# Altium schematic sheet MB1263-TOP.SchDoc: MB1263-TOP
size A3; CompanyName: STMicroelectronics; DocumentNumber: MB1263; Revision: C-04; SheetNumber: 2; SheetTotal: 11; Project: STM32MP157-EVAL
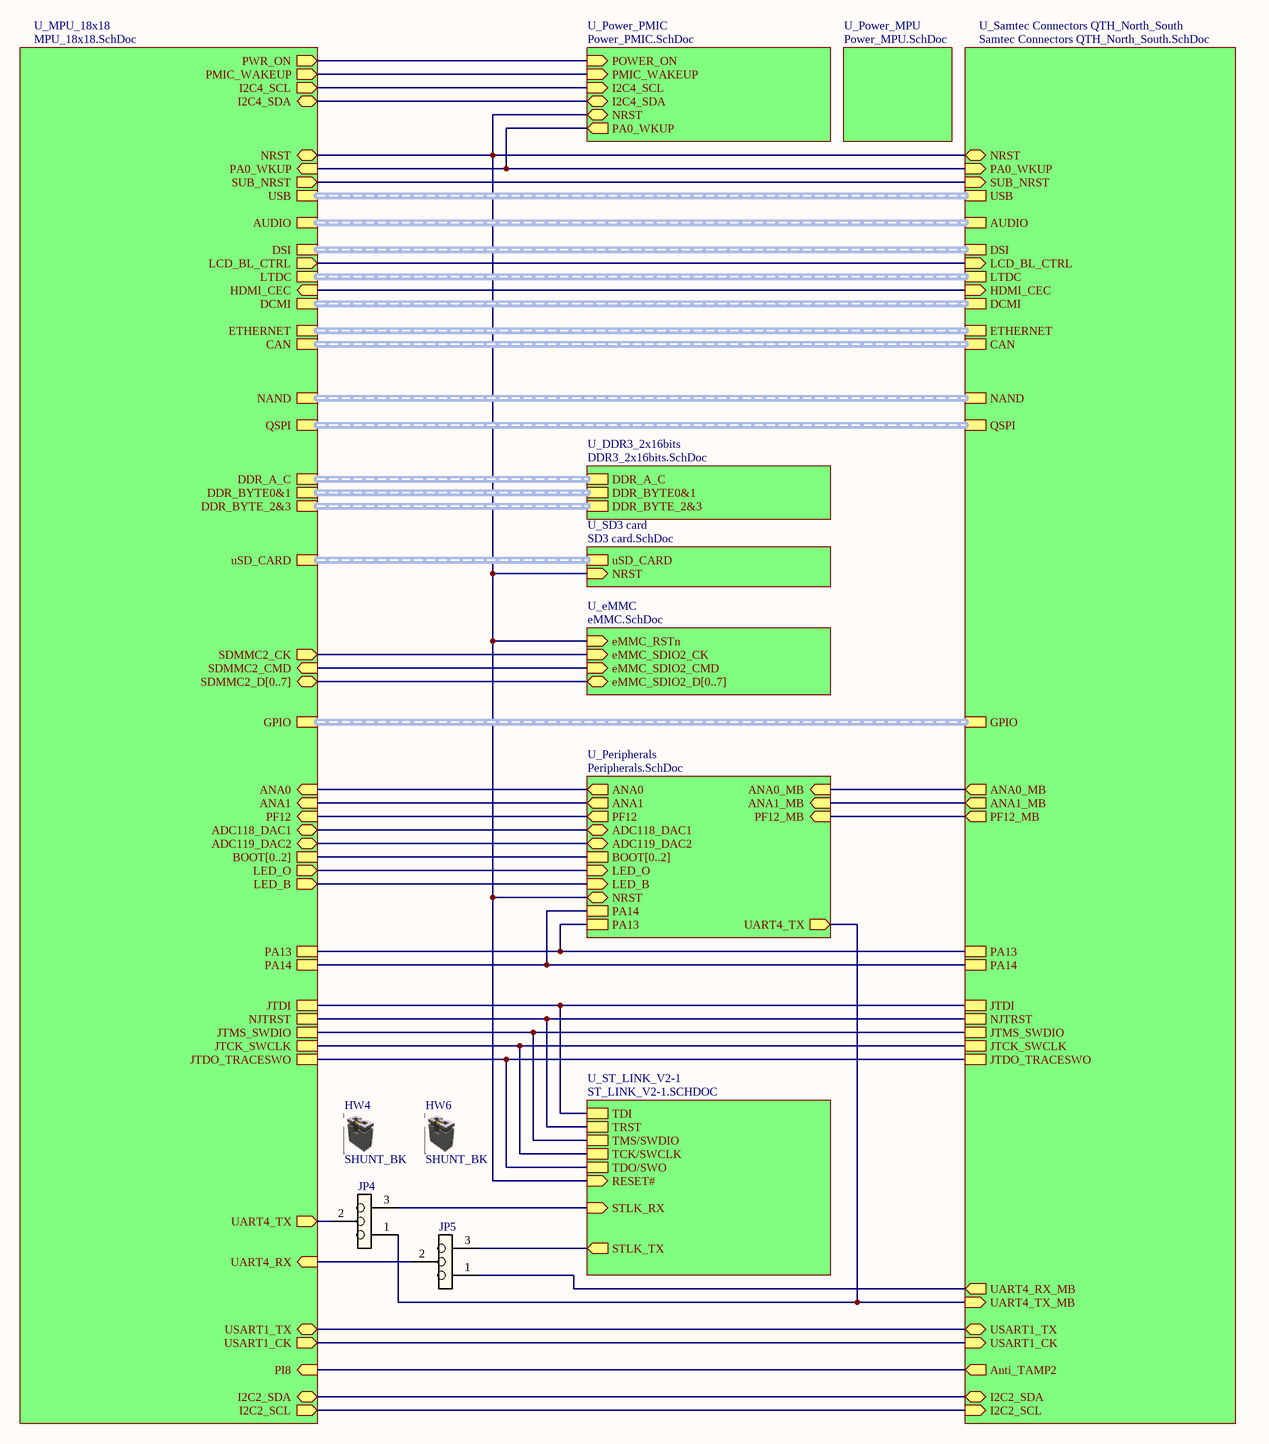
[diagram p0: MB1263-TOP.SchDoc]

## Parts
HW4  SHUNT_BK  (mechanical)
HW6  SHUNT_BK  (mechanical)
JP4  Header 3 pins  [CON_SAMTEC_TSW-103-07-F-S]  (value not drawn)
JP5  Header 3 pins  [CON_SAMTEC_TSW-103-07-F-S]  (value not drawn)

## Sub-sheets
U_DDR3_2x16bits = DDR3_2x16bits.SchDoc: DDR_A_C (harness DDR_A_C), DDR_BYTE0&1 (harness DDR_BYTE_0&1), DDR_BYTE_2&3 (harness DDR_BYTE_2&3)
U_eMMC = eMMC.SchDoc: eMMC_SDIO2_CK (in), eMMC_SDIO2_D[0..7] (bidir), eMMC_RSTn (in), eMMC_SDIO2_CMD (in)
U_MPU_18x18 = MPU_18x18.SchDoc: DDR_BYTE0&1 (harness DDR_BYTE_0&1), DDR_BYTE_2&3 (harness DDR_BYTE_2&3), DDR_A_C (harness DDR_A_C), ANA0 (in), ADC118_DAC1 (bidir), PWR_ON (out), SDMMC2_CK (out), SDMMC2_D[0..7] (bidir), SDMMC2_CMD (in), DSI (harness DSI), LCD_BL_CTRL (out), HDMI_CEC (in), USART1_TX (bidir), USART1_CK (out), CAN (harness CAN), JTMS_SWDIO, JTDI, JTDO_TRACESWO, NJTRST, JTCK_SWCLK, PA13, PA14, I2C4_SDA (bidir), I2C4_SCL (out), PA0_WKUP (in), PMIC_WAKEUP (out), NRST (bidir), UART4_TX (out), UART4_RX (in), ADC119_DAC2 (bidir), ANA1 (in), GPIO (harness GPIO), PI8 (in), USB (harness USB), NAND (harness NAND), LTDC (harness LTDC), DCMI (harness DCMI), ETHERNET (harness ETHERNET), QSPI (harness QSPI), AUDIO (harness AUDIO), uSD_CARD (harness uSD_CARD), PF12 (in), BOOT[0..2], I2C2_SDA (bidir), I2C2_SCL (out), LED_O (out), LED_B (out), SUB_NRST (out)
U_Peripherals = Peripherals.SchDoc: ADC118_DAC1 (bidir), ADC119_DAC2 (bidir), NRST (bidir), ANA0 (out), ANA1 (out), BOOT[0..2], PA13, PA14, UART4_TX (out), ANA0_MB (in), ANA1_MB (in), PF12 (out), PF12_MB (in), LED_O (in), LED_B (in)
U_Power_MPU = Power_MPU.SchDoc: no entries
U_Power_PMIC = Power_PMIC.SchDoc: I2C4_SDA (bidir), I2C4_SCL (in), PA0_WKUP (out), NRST (bidir), POWER_ON (in), PMIC_WAKEUP (in)
U_Samtec Connectors QTH_North_South = Samtec Connectors QTH_North_South.SchDoc: Anti_TAMP2 (out), USART1_TX (bidir), USART1_CK (in), GPIO (harness GPIO), LCD_BL_CTRL (in), DSI (harness DSI), JTMS_SWDIO, JTCK_SWCLK, JTDI, NJTRST, JTDO_TRACESWO, NRST (bidir), PA0_WKUP (in), CAN (harness CAN), UART4_TX_MB (in), UART4_RX_MB (out), PA13, PA14, HDMI_CEC (in), USB (harness USB), NAND (harness NAND), LTDC (harness LTDC), DCMI (harness DCMI), ETHERNET (harness ETHERNET), QSPI (harness QSPI), AUDIO (harness AUDIO), PF12_MB (out), ANA0_MB (out), ANA1_MB (out), I2C2_SCL (in), I2C2_SDA (bidir), SUB_NRST (in)
U_SD3 card = SD3 card.SchDoc: uSD_CARD (harness uSD_CARD), NRST (in)
U_ST_LINK_V2-1 = ST_LINK_V2-1.SCHDOC: STLK_RX (in), STLK_TX (out), TDI, TRST, TMS/SWDIO, TCK/SWCLK, TDO/SWO, RESET# (in)

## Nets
NetJP4_1: JP4.1 ; sheet U_Peripherals/UART4_TX, sheet U_Samtec Connectors QTH_North_South/UART4_TX_MB
NetJP4_2: JP4.2 ; sheet U_MPU_18x18/UART4_TX
NetJP4_3: JP4.3 ; sheet U_ST_LINK_V2-1/STLK_RX
NetJP5_1: JP5.1 ; sheet U_Samtec Connectors QTH_North_South/UART4_RX_MB
NetJP5_2: JP5.2 ; sheet U_MPU_18x18/UART4_RX
NetJP5_3: JP5.3 ; sheet U_ST_LINK_V2-1/STLK_TX
(unnamed): sheet U_eMMC/eMMC_SDIO2_CK, sheet U_MPU_18x18/SDMMC2_CK
(unnamed): sheet U_eMMC/eMMC_RSTn, sheet U_Power_PMIC/NRST, sheet U_MPU_18x18/NRST, sheet U_SD3 card/NRST, sheet U_Peripherals/NRST, sheet U_ST_LINK_V2-1/RESET#, sheet U_Samtec Connectors QTH_North_South/NRST  [a separate net that carries the same name]
(unnamed): sheet U_eMMC/eMMC_SDIO2_CMD, sheet U_MPU_18x18/SDMMC2_CMD  [a separate net that carries the same name]
(unnamed): sheet U_Power_PMIC/I2C4_SDA, sheet U_MPU_18x18/I2C4_SDA  [a separate net that carries the same name]
(unnamed): sheet U_Power_PMIC/I2C4_SCL, sheet U_MPU_18x18/I2C4_SCL  [a separate net that carries the same name]
(unnamed): sheet U_Power_PMIC/PA0_WKUP, sheet U_MPU_18x18/PA0_WKUP, sheet U_Samtec Connectors QTH_North_South/PA0_WKUP  [a separate net that carries the same name]
(unnamed): sheet U_Power_PMIC/POWER_ON, sheet U_MPU_18x18/PWR_ON  [a separate net that carries the same name]
(unnamed): sheet U_Power_PMIC/PMIC_WAKEUP, sheet U_MPU_18x18/PMIC_WAKEUP  [a separate net that carries the same name]
(unnamed): sheet U_MPU_18x18/ANA0, sheet U_Peripherals/ANA0  [a separate net that carries the same name]
(unnamed): sheet U_MPU_18x18/ADC118_DAC1, sheet U_Peripherals/ADC118_DAC1  [a separate net that carries the same name]
(unnamed): sheet U_MPU_18x18/LCD_BL_CTRL, sheet U_Samtec Connectors QTH_North_South/LCD_BL_CTRL  [a separate net that carries the same name]
(unnamed): sheet U_MPU_18x18/HDMI_CEC, sheet U_Samtec Connectors QTH_North_South/HDMI_CEC  [a separate net that carries the same name]
(unnamed): sheet U_MPU_18x18/USART1_TX, sheet U_Samtec Connectors QTH_North_South/USART1_TX  [a separate net that carries the same name]
(unnamed): sheet U_MPU_18x18/USART1_CK, sheet U_Samtec Connectors QTH_North_South/USART1_CK  [a separate net that carries the same name]
(unnamed): sheet U_MPU_18x18/JTMS_SWDIO, sheet U_ST_LINK_V2-1/TMS/SWDIO, sheet U_Samtec Connectors QTH_North_South/JTMS_SWDIO  [a separate net that carries the same name]
(unnamed): sheet U_MPU_18x18/JTDI, sheet U_ST_LINK_V2-1/TDI, sheet U_Samtec Connectors QTH_North_South/JTDI  [a separate net that carries the same name]
(unnamed): sheet U_MPU_18x18/JTDO_TRACESWO, sheet U_ST_LINK_V2-1/TDO/SWO, sheet U_Samtec Connectors QTH_North_South/JTDO_TRACESWO  [a separate net that carries the same name]
(unnamed): sheet U_MPU_18x18/NJTRST, sheet U_ST_LINK_V2-1/TRST, sheet U_Samtec Connectors QTH_North_South/NJTRST  [a separate net that carries the same name]
(unnamed): sheet U_MPU_18x18/JTCK_SWCLK, sheet U_ST_LINK_V2-1/TCK/SWCLK, sheet U_Samtec Connectors QTH_North_South/JTCK_SWCLK  [a separate net that carries the same name]
(unnamed): sheet U_MPU_18x18/PA13, sheet U_Peripherals/PA13, sheet U_Samtec Connectors QTH_North_South/PA13  [a separate net that carries the same name]
(unnamed): sheet U_MPU_18x18/PA14, sheet U_Peripherals/PA14, sheet U_Samtec Connectors QTH_North_South/PA14  [a separate net that carries the same name]
(unnamed): sheet U_MPU_18x18/ADC119_DAC2, sheet U_Peripherals/ADC119_DAC2  [a separate net that carries the same name]
(unnamed): sheet U_MPU_18x18/ANA1, sheet U_Peripherals/ANA1  [a separate net that carries the same name]
(unnamed): sheet U_MPU_18x18/PI8, sheet U_Samtec Connectors QTH_North_South/Anti_TAMP2  [a separate net that carries the same name]
(unnamed): sheet U_MPU_18x18/PF12, sheet U_Peripherals/PF12  [a separate net that carries the same name]
(unnamed): sheet U_MPU_18x18/I2C2_SDA, sheet U_Samtec Connectors QTH_North_South/I2C2_SDA  [a separate net that carries the same name]
(unnamed): sheet U_MPU_18x18/I2C2_SCL, sheet U_Samtec Connectors QTH_North_South/I2C2_SCL  [a separate net that carries the same name]
(unnamed): sheet U_MPU_18x18/LED_O, sheet U_Peripherals/LED_O  [a separate net that carries the same name]
(unnamed): sheet U_MPU_18x18/LED_B, sheet U_Peripherals/LED_B  [a separate net that carries the same name]
(unnamed): sheet U_MPU_18x18/SUB_NRST, sheet U_Samtec Connectors QTH_North_South/SUB_NRST  [a separate net that carries the same name]
(unnamed): sheet U_Peripherals/ANA0_MB, sheet U_Samtec Connectors QTH_North_South/ANA0_MB  [a separate net that carries the same name]
(unnamed): sheet U_Peripherals/ANA1_MB, sheet U_Samtec Connectors QTH_North_South/ANA1_MB  [a separate net that carries the same name]
(unnamed): sheet U_Peripherals/PF12_MB, sheet U_Samtec Connectors QTH_North_South/PF12_MB  [a separate net that carries the same name]

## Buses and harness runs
bus sheet U_eMMC/eMMC_SDIO2_D[0..7] = sheet U_MPU_18x18/SDMMC2_D[0..7]
bus sheet U_MPU_18x18/BOOT[0..2] = sheet U_Peripherals/BOOT[0..2]
harness sheet U_DDR3_2x16bits/DDR_A_C = sheet U_MPU_18x18/DDR_A_C
harness sheet U_DDR3_2x16bits/DDR_BYTE0&1 = sheet U_MPU_18x18/DDR_BYTE0&1
harness sheet U_DDR3_2x16bits/DDR_BYTE_2&3 = sheet U_MPU_18x18/DDR_BYTE_2&3
harness sheet U_MPU_18x18/AUDIO = sheet U_Samtec Connectors QTH_North_South/AUDIO
harness sheet U_MPU_18x18/CAN = sheet U_Samtec Connectors QTH_North_South/CAN
harness sheet U_MPU_18x18/DCMI = sheet U_Samtec Connectors QTH_North_South/DCMI
harness sheet U_MPU_18x18/DSI = sheet U_Samtec Connectors QTH_North_South/DSI
harness sheet U_MPU_18x18/ETHERNET = sheet U_Samtec Connectors QTH_North_South/ETHERNET
harness sheet U_MPU_18x18/GPIO = sheet U_Samtec Connectors QTH_North_South/GPIO
harness sheet U_MPU_18x18/LTDC = sheet U_Samtec Connectors QTH_North_South/LTDC
harness sheet U_MPU_18x18/NAND = sheet U_Samtec Connectors QTH_North_South/NAND
harness sheet U_MPU_18x18/QSPI = sheet U_Samtec Connectors QTH_North_South/QSPI
harness sheet U_MPU_18x18/USB = sheet U_Samtec Connectors QTH_North_South/USB
harness sheet U_MPU_18x18/uSD_CARD = sheet U_SD3 card/uSD_CARD

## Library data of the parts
HW4 HW6 = Shunt 2.54mm: SHUNT 2.54mm BLACK; Manuf_1: SAMTEC; Manuf_Part_1: SNT-100-BK-G; Fitted: YES; Ordered_By: Subcon
JP4 JP5 = Header 3: Header, 3-Pin; Manuf_1: Samtec; Manuf_Part_1: TSW-103-07-F-S; Fitted: YES; Ordered_By: Subcon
